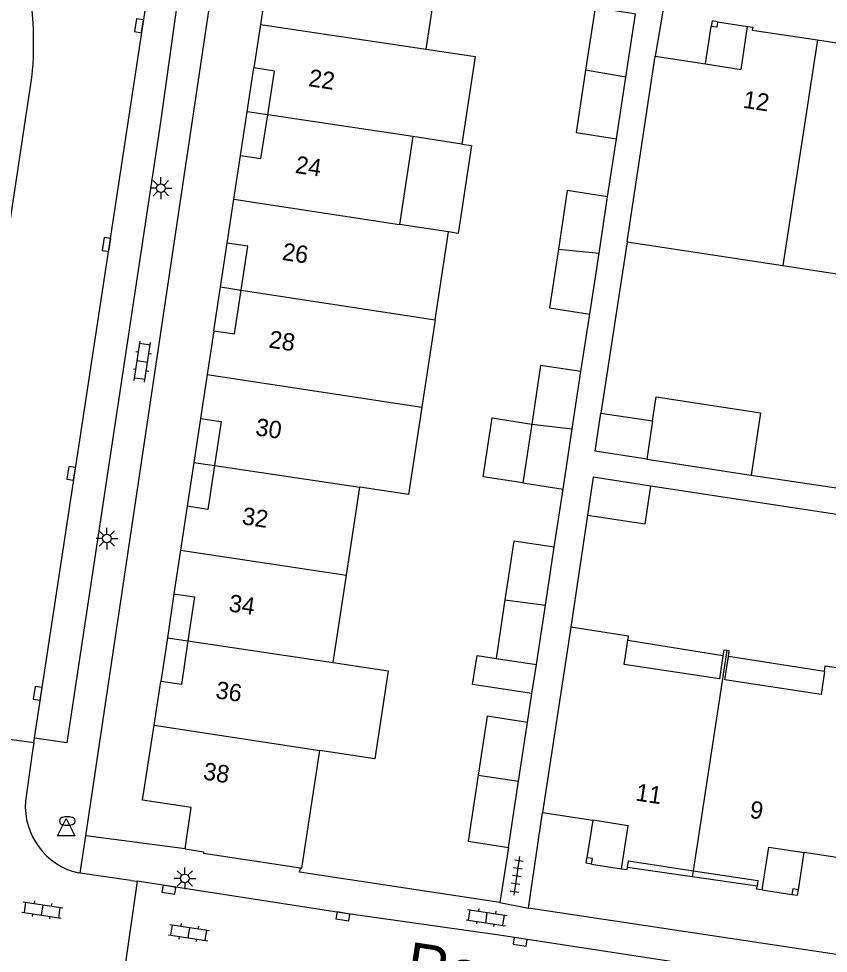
# Model space of a CAD drawing. Extents: x 124000 to 128010, y 398999 to 403000.
# Drawn here: x 126578 to 126624.6, y 400057.2 to 400110.9 of the extents above; entities that cross this region are included whole.
import ezdxf

# ---------------------------------------------------------------- set-up
doc = ezdxf.new("R2010")
doc.units = 0
for name, color, linetype in [('gg-afsc-erfafscheiding', 7, 'Continuous'), ('gg-afsc-muur', 7, 'Continuous'), ('gg-anno-huisnummerreeks BGT', 7, 'Continuous'), ('gg-anno-openbare ruimte label', 7, 'Continuous'), ('gg-bbg-bijgebouw', 7, 'Continuous'), ('gg-bbg-gedigitaliseerde bebouwing', 7, 'Continuous'), ('gg-bbg-hoofdgebouw', 7, 'Continuous'), ('gg-bbg-luifel en loopbrug', 7, 'Continuous'), ('gg-bbg-onder overbouw', 7, 'Continuous'), ('gg-bbg-pand overbouw', 7, 'Continuous'), ('gg-bbg-pilaar onder overbouw', 7, 'Continuous'), ('gg-bbg-pilaar pand', 7, 'Continuous'), ('gg-bbg-tussenscheiding', 7, 'Continuous'), ('gg-bbg-tussenscheiding niveau 01', 7, 'Continuous'), ('gg-knt-verharding', 7, 'Continuous'), ('gg-knt-verharding nz', 7, 'Continuous'), ('gt-grn-weggrens', 7, 'Continuous'), ('gt-symb-brandkraan', 7, 'Continuous'), ('gt-symb-klinker verharding', 7, 'Continuous'), ('gt-symb-kolk', 7, 'Continuous'), ('gt-symb-lichtmast', 7, 'Continuous'), ('gt-symb-tegel verharding', 7, 'Continuous'), ('gt-symb-waterafsluiter', 7, 'Continuous')]:
    doc.layers.add(name, color=color, linetype=linetype)

# ---------------------------------------------------------------- blocks, each defined once
blk = doc.blocks.new('gt0-KOLK')
at = {"layer": 'gt-symb-kolk'}
blk.add_lwpolyline([(0, 0), (0.375, 0), (0.375, 0.4), (-0.375, 0.4), (-0.375, 0), (0, 0)], dxfattribs=at)
blk = doc.blocks.new('gt0-KL1')
at = {"layer": 'gt-symb-klinker verharding'}
for p, q in [((-1.15, 0.3), (1.15, 0.3)), ((-1, -0.3), (-1, 0.3)), ((-0.5, 0.3), (-0.5, 0.45)), ((0, -0.3), (0, 0.3)), ((0.5, 0.3), (0.5, 0.45)), ((1, -0.3), (1, 0.3)), ((-1.15, -0.3), (1.15, -0.3)), ((-0.5, -0.45), (-0.5, -0.3)), ((0.5, -0.45), (0.5, -0.3))]:
    blk.add_line(p, q, dxfattribs=at)
blk = doc.blocks.new('gt0-TEG1')
at = {"layer": 'gt-symb-tegel verharding'}
for p, q in [((-1.125, 0), (1.125, 0)), ((-0.9, -0.25), (-0.9, 0.25)), ((-0.45, -0.25), (-0.45, 0.25)), ((0, -0.25), (0, 0.25)), ((0.45, -0.25), (0.45, 0.25)), ((0.9, -0.25), (0.9, 0.25))]:
    blk.add_line(p, q, dxfattribs=at)
blk = doc.blocks.new('gt0-LMAST')
at = {"layer": 'gt-symb-lichtmast'}
for p, q in [((-0.005, 0.246), (-0.005, 0.621)), ((-0.182, 0.173), (-0.447, 0.438)), ((0.172, 0.173), (0.437, 0.438)), ((-0.255, -0.004), (-0.63, -0.004)), ((-0.182, -0.181), (-0.447, -0.446)), ((-0.005, -0.254), (-0.005, -0.629)), ((0.437, -0.446), (0.172, -0.181)), ((0.245, -0.004), (0.62, -0.004))]:
    blk.add_line(p, q, dxfattribs=at)
blk.add_circle((-0.005, -0.004), 0.25, dxfattribs=at)
blk = doc.blocks.new('gt0-WAFSL')
at = {"layer": 'gt-symb-waterafsluiter'}
for p, q in [((-0.5, -0.333), (0, 0.667)), ((0, 0.667), (0.5, -0.333)), ((0.5, -0.333), (-0.5, -0.333))]:
    blk.add_line(p, q, dxfattribs=at)
blk = doc.blocks.new('gt0-BR')
at = {"layer": 'gt-symb-brandkraan'}
for centre, radius, start, end in [((-0.244, 0), 0.206, 107.5669, 252.4331), ((0.599, -2.664), 3, 106.892, 107.5669), ((0, -0.691), 0.938, 73.108, 106.892), ((-0.599, -2.664), 3, 72.4331, 73.108), ((0.244, 0), 0.206, 287.567, 72.4331), ((0.599, 2.664), 3, 252.4331, 253.108), ((0, 0.691), 0.938, 253.108, 286.8921), ((-0.599, 2.664), 3, 286.8921, 287.567)]:
    blk.add_arc(centre, radius, start, end, dxfattribs=at)

msp = doc.modelspace()

# ---------------------------------------------------------------- linework, layer by layer
at = {"layer": 'gg-afsc-erfafscheiding'}
for p, q in [((126611.921, 400100.695), (126612.43, 400104.032)), ((126613.036, 400098.095), (126611.538, 400088.238)), ((126610.387, 400090.631), (126610.891, 400093.938)), ((126620.187, 400084.678), (126626.016, 400083.793)), ((126608.846, 400080.518), (126609.358, 400083.874)), ((126625.922, 400082.287), (126614.412, 400084.042)), ((126610.756, 400082.366), (126609.8, 400075.921)), ((126607.311, 400070.445), (126607.565, 400072.108))]:
    msp.add_line(p, q, dxfattribs=at)
at = {"layer": 'gg-afsc-muur'}
msp.add_line((126606.215, 400063.253), (126605.708, 400060.071), dxfattribs=at)
msp.add_lwpolyline([(126605.708, 400060.071), (126594.176, 400061.818), (126594.233, 400062.068)], dxfattribs=at)
at = {"layer": 'gg-bbg-bijgebouw'}
for p, q in [((126612.43, 400104.032), (126612.969, 400107.571)), ((126611.425, 400097.439), (126611.921, 400100.695)), ((126610.891, 400093.938), (126611.425, 400097.439)), ((126609.886, 400087.338), (126610.387, 400090.631)), ((126611.538, 400088.238), (126614.504, 400087.788)), ((126607.55, 400087.612), (126607.034, 400084.229)), ((126614.504, 400087.788), (126614.171, 400085.592)), ((126609.358, 400083.874), (126609.886, 400087.338)), ((126607.034, 400084.229), (126609.358, 400083.874)), ((126608.34, 400077.197), (126608.846, 400080.518)), ((126606.009, 400077.499), (126605.495, 400074.125)), ((126607.818, 400073.771), (126608.34, 400077.197)), ((126605.495, 400074.125), (126607.818, 400073.771)), ((126606.796, 400067.066), (126607.311, 400070.445)), ((126606.215, 400063.253), (126606.796, 400067.066))]:
    msp.add_line(p, q, dxfattribs=at)
for points in [[(126613.452, 400111.215), (126611.2, 400111.558), (126610.654, 400107.977)], [(126612.969, 400107.571), (126613.523, 400111.204), (126613.452, 400111.215)], [(126610.654, 400107.977), (126610.106, 400104.386), (126612.43, 400104.032)], [(126611.921, 400100.695), (126609.598, 400101.049), (126609.084, 400097.675)], [(126609.084, 400097.675), (126608.568, 400094.292), (126610.891, 400093.938)], [(126610.387, 400090.631), (126608.064, 400090.985), (126607.55, 400087.612)], [(126614.171, 400085.592), (126611.205, 400086.043), (126611.538, 400088.238)], [(126614.412, 400084.042), (126611.087, 400084.547), (126610.756, 400082.366)], [(126610.756, 400082.366), (126614.081, 400081.861), (126614.412, 400084.042)], [(126608.846, 400080.518), (126606.523, 400080.872), (126606.009, 400077.499)], [(126607.311, 400070.445), (126604.988, 400070.799), (126604.471, 400067.406)], [(126604.471, 400067.406), (126603.892, 400063.607), (126606.215, 400063.253)]]:
    msp.add_lwpolyline(points, dxfattribs=at)
at = {"layer": 'gg-bbg-gedigitaliseerde bebouwing'}
for p, q in [((126600.71, 400104.149), (126599.943, 400099.095)), ((126603.532, 400103.726), (126600.71, 400104.149)), ((126602.753, 400098.666), (126599.943, 400099.095)), ((126601.982, 400093.613), (126602.753, 400098.666)), ((126601.982, 400093.613), (126601.215, 400088.588)), ((126596.878, 400078.909), (126597.647, 400083.973)), ((126596.115, 400073.884), (126596.878, 400078.909)), ((126594.319, 400062.055), (126595.348, 400068.83))]:
    msp.add_line(p, q, dxfattribs=at)
for points in [[(126601.473, 400109.177), (126604.285, 400108.756), (126603.532, 400103.726)], [(126601.215, 400088.588), (126600.461, 400083.552), (126597.647, 400083.973)], [(126596.115, 400073.884), (126599.289, 400073.401), (126598.519, 400068.347), (126595.348, 400068.83)]]:
    msp.add_lwpolyline(points, dxfattribs=at)
at = {"layer": 'gg-bbg-hoofdgebouw'}
for p, q in [((126591.936, 400110.606), (126591.557, 400108.106)), ((126613.036, 400098.095), (126614.658, 400108.772)), ((126614.658, 400108.772), (126617.553, 400108.331)), ((126590.401, 400100.547), (126590.783, 400103.07)), ((126590.02, 400098.025), (126590.401, 400100.547)), ((126613.036, 400098.095), (126622.017, 400096.73)), ((126622.017, 400096.73), (126630.978, 400095.369)), ((126589.256, 400092.983), (126588.872, 400090.46)), ((126588.872, 400090.46), (126588.487, 400087.928)), ((126587.72, 400082.88), (126587.337, 400080.356)), ((126587.337, 400080.356), (126586.954, 400077.835)), ((126609.8, 400075.921), (126608.168, 400065.26)), ((126585.81, 400070.282), (126586.195, 400072.802)), ((126608.168, 400065.26), (126611.071, 400064.822)), ((126626.13, 400062.517), (126623.231, 400062.956)), ((126594.233, 400062.068), (126594.319, 400062.055))]:
    msp.add_line(p, q, dxfattribs=at)
for points in [[(126595.763, 400116.894), (126595.365, 400114.497), (126592.591, 400114.93), (126591.936, 400110.606)], [(126601.473, 400109.177), (126602.503, 400115.959), (126602.347, 400115.983)], [(126619.976, 400110.491), (126620.29, 400110.445), (126620.251, 400110.283), (126624.001, 400109.715)], [(126624.001, 400109.715), (126627.709, 400109.153), (126627.732, 400109.311), (126628.057, 400109.263)], [(126613.081, 400075.152), (126613.121, 400075.415), (126609.8, 400075.921)], [(126618.789, 400074.573), (126618.612, 400074.599), (126618.562, 400074.269)], [(126618.873, 400074.226), (126618.923, 400074.553), (126618.789, 400074.573)], [(126624.409, 400073.378), (126624.444, 400073.705), (126627.765, 400073.198)], [(126587.602, 400063.162), (126587.95, 400065.552), (126585.151, 400065.976), (126585.81, 400070.282)], [(126587.602, 400063.162), (126588.654, 400062.993), (126588.656, 400062.926), (126594.233, 400062.068)], [(126612.717, 400062.016), (126613.047, 400061.982), (126613.064, 400062.095)], [(126620.809, 400060.804), (126620.5, 400060.852), (126620.526, 400061.02)]]:
    msp.add_lwpolyline(points, dxfattribs=at)
at = {"layer": 'gg-bbg-luifel en loopbrug'}
for p, q in [((126614.171, 400085.592), (126620.187, 400084.678)), ((126607.565, 400072.108), (126607.818, 400073.771))]:
    msp.add_line(p, q, dxfattribs=at)
for points in [[(126603.532, 400103.726), (126604.09, 400103.641), (126603.317, 400098.579), (126602.753, 400098.666)], [(126614.504, 400087.788), (126614.714, 400089.173), (126620.731, 400088.259), (126620.187, 400084.678)], [(126607.034, 400084.229), (126604.756, 400084.577), (126605.273, 400087.96), (126607.55, 400087.612)], [(126607.565, 400072.108), (126604.147, 400072.63), (126604.401, 400074.292), (126605.495, 400074.125)]]:
    msp.add_lwpolyline(points, dxfattribs=at)
at = {"layer": 'gg-bbg-onder overbouw'}
for points in [[(126617.553, 400108.331), (126619.6, 400108.02), (126619.976, 400110.491)], [(126592.352, 400105.404), (126592.743, 400107.926), (126591.557, 400108.106)], [(126590.783, 400103.07), (126591.963, 400102.893), (126592.352, 400105.404)], [(126590.82, 400095.317), (126591.207, 400097.846), (126590.02, 400098.025)], [(126589.256, 400092.983), (126590.435, 400092.798), (126590.82, 400095.317)], [(126588.487, 400087.928), (126589.667, 400087.754), (126589.282, 400085.227)], [(126589.282, 400085.227), (126588.897, 400082.701), (126587.72, 400082.88)], [(126586.954, 400077.835), (126588.138, 400077.667), (126587.758, 400075.134)], [(126587.758, 400075.134), (126587.381, 400072.621), (126586.195, 400072.802)], [(126618.562, 400074.269), (126618.361, 400072.95), (126612.871, 400073.774), (126613.081, 400075.152)], [(126624.409, 400073.378), (126624.21, 400072.057), (126618.67, 400072.892), (126618.873, 400074.226)], [(126612.717, 400062.016), (126613.104, 400064.499), (126611.071, 400064.822)], [(126620.809, 400060.804), (126621.211, 400063.262), (126623.231, 400062.956)], [(126613.064, 400062.095), (126613.119, 400062.469), (126616.85, 400061.904)], [(126616.85, 400061.904), (126620.575, 400061.34), (126620.526, 400061.02)]]:
    msp.add_lwpolyline(points, dxfattribs=at)
at = {"layer": 'gg-bbg-pand overbouw'}
for p, q in [((126618.247, 400110.758), (126619.976, 400110.491)), ((126617.553, 400108.331), (126617.883, 400110.49)), ((126591.169, 400105.582), (126591.557, 400108.106)), ((126590.783, 400103.07), (126591.169, 400105.582)), ((126589.637, 400095.498), (126590.02, 400098.025)), ((126589.256, 400092.983), (126589.637, 400095.498)), ((126588.487, 400087.928), (126588.103, 400085.404)), ((126588.103, 400085.404), (126587.72, 400082.88)), ((126586.954, 400077.835), (126586.573, 400075.311)), ((126586.573, 400075.311), (126586.195, 400072.802)), ((126618.562, 400074.269), (126613.081, 400075.152)), ((126624.409, 400073.378), (126618.873, 400074.226)), ((126611.071, 400064.822), (126610.73, 400062.656)), ((126622.902, 400060.806), (126623.231, 400062.956)), ((126610.997, 400062.289), (126612.717, 400062.016)), ((126616.797, 400061.557), (126613.064, 400062.095)), ((126620.526, 400061.02), (126616.797, 400061.557)), ((126620.809, 400060.804), (126622.534, 400060.548))]:
    msp.add_line(p, q, dxfattribs=at)
at = {"layer": 'gg-bbg-pilaar onder overbouw'}
for points in [[(126618.247, 400110.758), (126618.199, 400110.441), (126617.883, 400110.49)], [(126610.997, 400062.289), (126611.047, 400062.606), (126610.73, 400062.656)], [(126622.902, 400060.806), (126622.585, 400060.857), (126622.534, 400060.548)]]:
    msp.add_lwpolyline(points, dxfattribs=at)
at = {"layer": 'gg-bbg-pilaar pand'}
for points in [[(126618.247, 400110.758), (126617.931, 400110.806), (126617.883, 400110.49)], [(126610.997, 400062.289), (126610.681, 400062.34), (126610.73, 400062.656)], [(126622.534, 400060.548), (126622.852, 400060.496), (126622.902, 400060.806)]]:
    msp.add_lwpolyline(points, dxfattribs=at)
at = {"layer": 'gg-bbg-tussenscheiding'}
for p, q in [((126591.936, 400110.606), (126601.473, 400109.177)), ((126624.001, 400109.715), (126622.017, 400096.73)), ((126612.969, 400107.571), (126610.654, 400107.977)), ((126600.71, 400104.149), (126592.352, 400105.404)), ((126590.401, 400100.547), (126599.943, 400099.095)), ((126609.084, 400097.675), (126611.425, 400097.439)), ((126590.82, 400095.317), (126601.982, 400093.613)), ((126588.872, 400090.46), (126601.215, 400088.588)), ((126607.55, 400087.612), (126609.886, 400087.338)), ((126589.282, 400085.227), (126597.647, 400083.973)), ((126587.337, 400080.356), (126596.878, 400078.909)), ((126606.009, 400077.499), (126608.34, 400077.197)), ((126587.758, 400075.134), (126596.115, 400073.884)), ((126618.789, 400074.573), (126616.85, 400061.904)), ((126585.81, 400070.282), (126595.348, 400068.83)), ((126604.471, 400067.406), (126606.796, 400067.066))]:
    msp.add_line(p, q, dxfattribs=at)
at = {"layer": 'gg-bbg-tussenscheiding niveau 01'}
for p, q in [((126592.352, 400105.404), (126591.169, 400105.582)), ((126589.637, 400095.498), (126590.82, 400095.317)), ((126588.103, 400085.404), (126589.282, 400085.227)), ((126586.573, 400075.311), (126587.758, 400075.134)), ((126616.85, 400061.904), (126616.797, 400061.557))]:
    msp.add_line(p, q, dxfattribs=at)
at = {"layer": 'gg-knt-verharding'}
for p, q in [((126581.871, 400063.921), (126589.953, 400118.108)), ((126615.58, 400114.21), (126614.658, 400108.772)), ((126572.978, 400070.109), (126578.892, 400069.278)), ((126578.892, 400069.278), (126578.932, 400069.527)), ((126607.368, 400059.761), (126608.168, 400065.26)), ((126587.602, 400063.162), (126581.871, 400063.921)), ((126584.836, 400061.298), (126584.105, 400056.219)), ((126605.708, 400060.071), (126607.368, 400059.761)), ((126661.242, 400051.623), (126607.368, 400059.761)), ((126630.844, 400054.355), (126605.67, 400058.209))]:
    msp.add_line(p, q, dxfattribs=at)
for points in [[(126585.535, 400112.994), (126587.245, 400112.694), (126586.187, 400104.986)], [(126586.187, 400104.986), (126580.779, 400069.263), (126578.932, 400069.527)], [(126605.67, 400058.209), (126596.709, 400059.464), (126584.836, 400061.298)]]:
    msp.add_lwpolyline(points, dxfattribs=at)
at = {"layer": 'gg-knt-verharding nz'}
for p, q in [((126578.844, 400110.681), (126578.577, 400114.363)), ((126578.932, 400069.527), (126585.535, 400112.994)), ((126574.902, 400082.036), (126578.775, 400107.551)), ((126578.892, 400069.278), (126578.815, 400068.805)), ((126578.815, 400068.805), (126578.404, 400065.909)), ((126581.553, 400061.766), (126581.448, 400061.781)), ((126584.47, 400061.354), (126581.553, 400061.766)), ((126584.47, 400061.354), (126584.836, 400061.298))]:
    msp.add_line(p, q, dxfattribs=at)
for centre, radius, start, end in [((126558.618, 400109.561), 20.257, 354.3051, 3.1691), ((126582.34, 400065.625), 3.946, 175.876, 256.9344)]:
    msp.add_arc(centre, radius, start, end, dxfattribs=at)
at = {"layer": 'gt-grn-weggrens'}
msp.add_line((126581.553, 400061.766), (126581.871, 400063.921), dxfattribs=at)

# ---------------------------------------------------------------- block references
at = {"layer": 'gt-symb-brandkraan'}
msp.add_blockref('gt0-BR', (126580.813, 400064.767), dxfattribs=at)
at = {"layer": 'gt-symb-klinker verharding'}
for p, rotation in [((126585.137, 400091.206), 81.48906580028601), ((126579.372, 400059.651), -8.510934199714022), ((126604.949, 400059.214), -8.567589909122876), ((126587.814, 400058.348), -8.680850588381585)]:
    msp.add_blockref('gt0-KL1', p, dxfattribs=dict(at, rotation=rotation))
at = {"layer": 'gt-symb-kolk'}
for p, rotation in [((126585.142, 400110.502), 81.19719553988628), ((126583.264, 400097.916), 81.19719554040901), ((126581.229, 400084.745), 81.19719554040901), ((126579.299, 400072.084), 81.19719553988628), ((126586.629, 400060.618), -9.556527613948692), ((126596.65, 400059.082), -9.556527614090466), ((126606.916, 400058.015), 171.2538377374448)]:
    msp.add_blockref('gt0-KOLK', p, dxfattribs=dict(at, rotation=rotation))
at = {"layer": 'gt-symb-lichtmast'}
for p in [(126586.209, 400101.188), (126583.098, 400081.025), (126587.588, 400061.472)]:
    msp.add_blockref('gt0-LMAST', p, dxfattribs=at)
at = {"layer": 'gt-symb-tegel verharding', "rotation": -98.56758990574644}
msp.add_blockref('gt0-TEG1', (126606.686, 400061.61), dxfattribs=at)
at = {"layer": 'gt-symb-waterafsluiter'}
msp.add_blockref('gt0-WAFSL', (126580.744, 400064.242), dxfattribs=at)

# ---------------------------------------------------------------- texts
at = {"layer": 'gg-anno-huisnummerreeks BGT'}
for s, rotation, p in [('22', 351.4, (126594.658, 400107.062)), ('12', 351.4, (126619.675, 400105.819)), ('24', 351.4, (126593.891, 400102.068)), ('26', 351.4, (126593.135, 400097.064)), ('28', 351.3, (126592.369, 400092.02)), ('30', 351.4, (126591.602, 400086.971)), ('32', 351.4, (126590.824, 400081.851)), ('34', 351.4, (126590.063, 400076.838)), ('36', 351.3, (126589.308, 400071.838)), ('38', 351.3, (126588.593, 400067.166)), ('11', 351.4, (126613.49, 400065.953)), ('9', 351.4, (126620.062, 400064.958))]:
    msp.add_text(s, height=1, rotation=rotation, dxfattribs=at).set_placement(p)
at = {"layer": 'gg-anno-openbare ruimte label'}
msp.add_text('Ransdorpstraat', height=2.5, rotation=351.4, dxfattribs=at).set_placement((126600.203, 400055.351))

doc.saveas('drawing.dxf')
